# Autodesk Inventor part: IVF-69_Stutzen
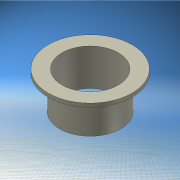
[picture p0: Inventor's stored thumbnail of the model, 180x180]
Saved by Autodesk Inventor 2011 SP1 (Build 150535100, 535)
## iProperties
Created: 2012-03
Part Number: IVF-69_Stutzen
Material: Standard
Document SubType Name: Blech
Designer: Gawin
Mass: 258.201 g
Surface Area: 937.313 cm^2
Volume: 258.201 cm^3
Density: 1 g/cm^3
Sheet Metal Rule: Standard_mm
Author: Gawin
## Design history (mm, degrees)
derived "IVF-69_Master.ipt"
revolve "Umdrehung1" stored, may be unused: angle "d1" = 90 deg
mirror "Spiegeln1"
feature "Volumenkörper1::IVF-69_Master.ipt" dims "d0" = 10
tag "Bezeichnung1"
sketch "Skizze7"
  geometry: L1 (-90.99, 142)-(-65.99, 142) reference; L2 (-65.99, 142)-(-65.99, 70) reference; L3 (-65.99, 70)-(-60.99, 70) reference; L4 (-60.99, 70)-(-60.99, 150) reference; L5 (-60.99, 150)-(-90.99, 150) reference; L6 (-90.99, 150)-(-90.99, 142) reference; L7 (0, -92)-(0, 202) reference; 2 further points
node "Volumenkörper1"
other parameters: "Stärke" = 4 (derived), "KFaktor" = 4.4, "Biegeradius" = 4 (= Stärke), "BreiteBiegungsfreistellung" = 4 (= Stärke), "TiefeBiegungsfreistellung" = 2 (= 0.5 x Stärke), "GrößeEckenfreistellung" = 16 (= 4 x Stärke), "AbstandVerbindung" = 0.01, "MinimalRest" = 8 (= 2 x Stärke), "Übergangsradius" = 4 (= Biegeradius), "JacobiRadiusGröße" = 4 (= Biegeradius), "Abstandsgröße" = 4 (= Stärke)
